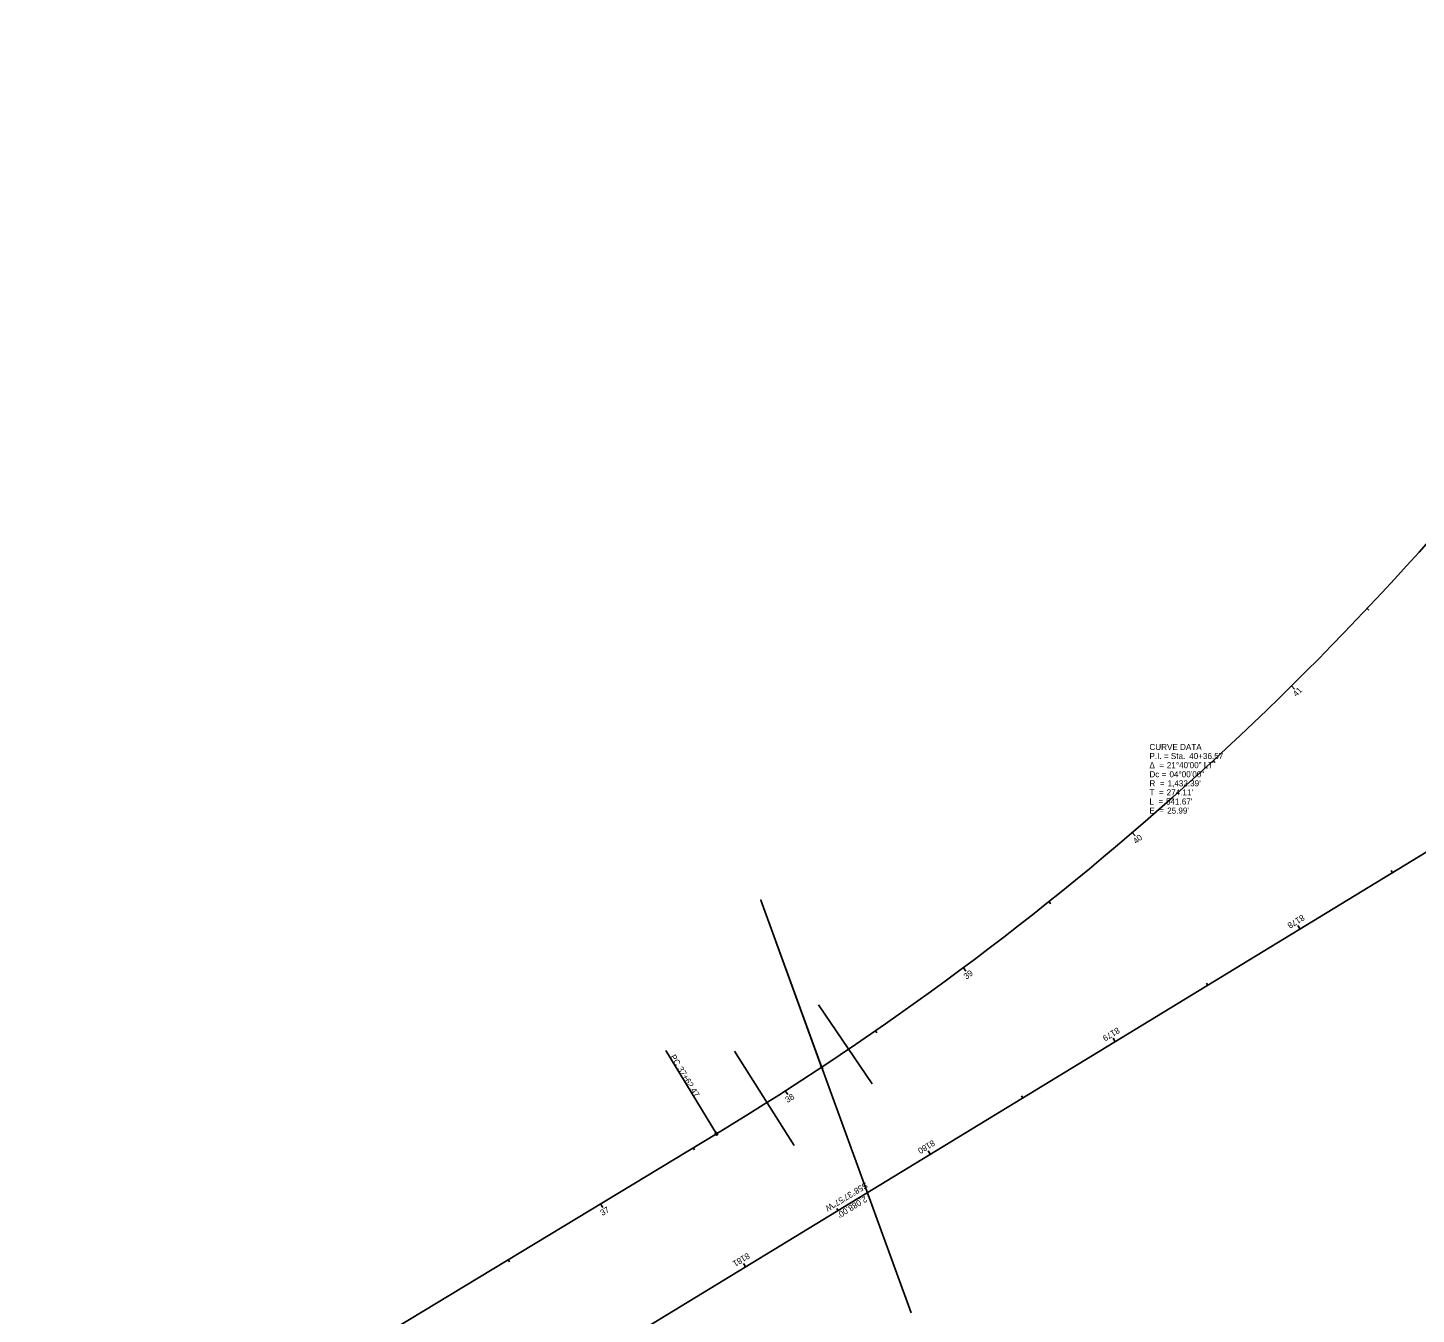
# Model space of a CAD drawing. Extents: x 2047945 to 2050534, y 355635 to 356996.
# Drawn here: x 2049240 to 2049881, y 356288 to 356882 of the extents above; entities that cross this region are included whole.
import ezdxf

# ---------------------------------------------------------------- set-up
doc = ezdxf.new("R2010")
doc.units = 0
for name, color, linetype in [('Default', 7, 'Continuous'), ('GE_X_Alignment_100_Bearings', 7, 'Continuous'), ('GE_X_Alignment_100_Cardinal_Points', 7, 'Continuous'), ('GE_X_Alignment_100_Curve_Data', 7, 'Continuous'), ('GE_X_Alignment_100_Distances', 7, 'Continuous'), ('GE_X_Alignment_100_Stations', 7, 'Continuous'), ('RW_X_CL', 7, 'Continuous'), ('SC_Scratch1', 7, 'Continuous'), ('SV_P_Control_Cells_Set', 7, 'Continuous')]:
    doc.layers.add(name, color=color, linetype=linetype)

msp = doc.modelspace()

# ---------------------------------------------------------------- linework, layer by layer
at = {"layer": 'Default'}
for p, q in [((2049629.85, 356393.93), (2049605.14, 356430.48)), ((2049566.36, 356409.09), (2049593.9, 356365.45))]:
    msp.add_line(p, q, dxfattribs=at)
at = {"layer": 'GE_X_Alignment_100_Cardinal_Points'}
msp.add_line((2049557.91, 356370.89), (2049534.62, 356409.4), dxfattribs=at)
msp.add_circle((2049557.91, 356370.89), 0.6, dxfattribs=at)
at = {"layer": 'GE_X_Alignment_100_Stations'}
for p, q in [((2049858.54, 356613.56), (2049859.42, 356612.74)), ((2049823.6, 356577.8), (2049825.01, 356576.38)), ((2049787.43, 356543.28), (2049788.24, 356542.4)), ((2049750.08, 356510.05), (2049751.38, 356508.53)), ((2049870.29, 356491.51), (2049869.67, 356492.53)), ((2049711.59, 356478.14), (2049712.34, 356477.2)), ((2049827.6, 356465.48), (2049826.56, 356467.19)), ((2049672.01, 356447.59), (2049673.2, 356445.99)), ((2049784.91, 356439.45), (2049784.28, 356440.48)), ((2049631.38, 356418.44), (2049632.07, 356417.46)), ((2049742.22, 356413.43), (2049741.18, 356415.14)), ((2049589.77, 356390.73), (2049590.85, 356389.05)), ((2049699.52, 356387.4), (2049698.9, 356388.43)), ((2049547.24, 356364.44), (2049547.86, 356363.42)), ((2049656.83, 356361.38), (2049655.79, 356363.08)), ((2049504.45, 356338.57), (2049505.49, 356336.86)), ((2049614.14, 356335.35), (2049613.52, 356336.37)), ((2049461.67, 356312.7), (2049462.29, 356311.67)), ((2049571.45, 356309.32), (2049570.41, 356311.03))]:
    msp.add_line(p, q, dxfattribs=at)
at = {"layer": 'RW_X_CL'}
for p, q in [((2050510.68, 356881.9), (2048727.85, 355795.04)), ((2049203.63, 356156.68), (2049557.91, 356370.89))]:
    msp.add_line(p, q, dxfattribs=at)
msp.add_arc((2048816.77, 357596.64), 1432.39, 301.15897, 322.82564, dxfattribs=at)
at = {"layer": 'SC_Scratch1'}
msp.add_line((2049578.38, 356478.83), (2049647.91, 356288.2), dxfattribs=at)
msp.add_lwpolyline([(2049606.53, 356401.64), (2049578.38, 356478.83), (2049647.91, 356288.2)], dxfattribs=at)
at = {"layer": 'SV_P_Control_Cells_Set'}
for p, q in [((2049607.2, 356400.98), (2049605.86, 356402.31)), ((2049605.86, 356400.98), (2049607.2, 356402.31))]:
    msp.add_line(p, q, dxfattribs=at)

# ---------------------------------------------------------------- texts
at = {"layer": 'GE_X_Alignment_100_Bearings'}
msp.add_text('S58°37\'57"W', height=2.8, rotation=211.36741, dxfattribs=at).set_placement((2049626.8, 356348.69))
at = {"layer": 'GE_X_Alignment_100_Cardinal_Points'}
for s, p in [('PC', (2049536.45, 356406.47)), ('37+62.47', (2049539.83, 356400.89))]:
    msp.add_text(s, height=2.8, rotation=301.15897, dxfattribs=at).set_placement(p)
at = {"layer": 'GE_X_Alignment_100_Curve_Data'}
for s, p in [('CURVE DATA', (2049758, 356548.21)), ('Δ  = ', (2049758, 356539.81)), ('P.I. = Sta. ', (2049758, 356544.01)), ('21°40\'00" LT', (2049766.03, 356539.81)), ('40+36.57', (2049776.37, 356544.01)), ('Dc = ', (2049758, 356535.61)), ('04°00\'00"', (2049767.24, 356535.61)), ('T  = ', (2049758, 356527.21)), ('R  = ', (2049758, 356531.41)), ("274.11'", (2049765.94, 356527.21)), ("1,432.39'", (2049766.37, 356531.41)), ('L  = ', (2049758, 356523.01)), ("541.67'", (2049765.65, 356523.01)), ('E  = ', (2049758, 356518.81)), ("25.99'", (2049766.16, 356518.81))]:
    msp.add_text(s, height=2.8, dxfattribs=at).set_placement(p)
at = {"layer": 'GE_X_Alignment_100_Distances'}
msp.add_text("2,088.00'", height=2.8, rotation=211.36741, dxfattribs=at).set_placement((2049626.49, 356342.22))
at = {"layer": 'GE_X_Alignment_100_Stations'}
for s, rotation, p in [('41', 44.6603, (2049825.89, 356572.61)), ('40', 40.6603, (2049751.87, 356504.6)), ('8178', 211.36741, (2049828.57, 356472.28)), ('39', 36.6603, (2049673.43, 356442.05)), ('8179', 211.36741, (2049743.16, 356420.21)), ('38', 32.66029, (2049590.78, 356385.09)), ('8180', 211.36741, (2049657.8, 356368.17)), ('37', 31.15897, (2049505.27, 356332.87)), ('8181', 211.36741, (2049572.27, 356316.03))]:
    msp.add_text(s, height=2.8, rotation=rotation, dxfattribs=at).set_placement(p)

doc.saveas('drawing.dxf')
